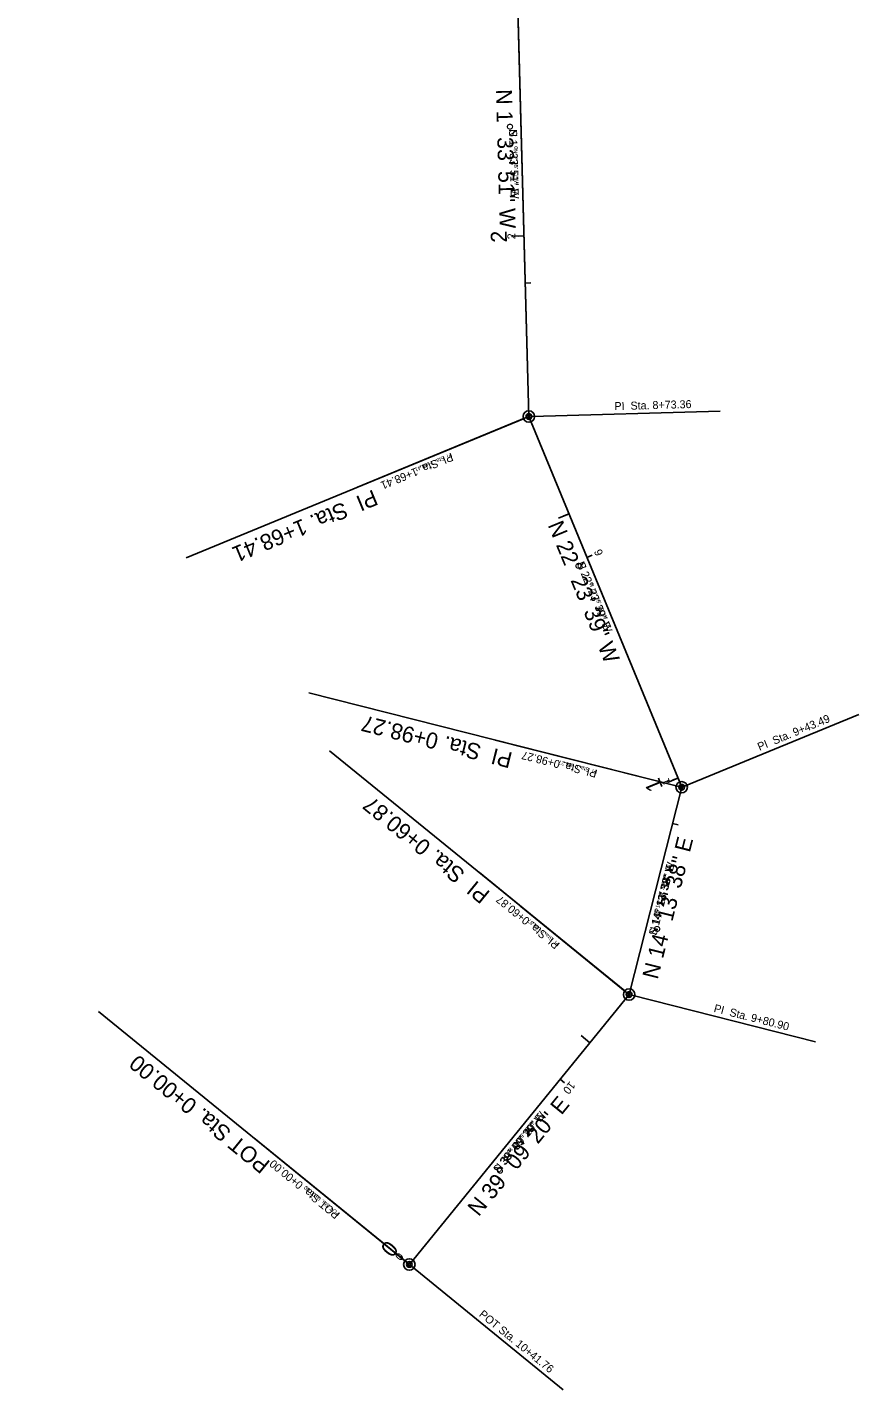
# Model space of a CAD drawing. Extents: x 2261207 to 2264340, y 653057 to 655601.
# Drawn here: x 2261628.8 to 2261774.1, y 654744.8 to 654983.1 of the extents above; entities that cross this region are included whole.
import ezdxf

# ---------------------------------------------------------------- set-up
doc = ezdxf.new("R2010")
doc.units = 0
for name, color, linetype in [('CL_X_Construction', 7, 'Continuous'), ('Default', 7, 'Continuous'), ('GE_X_CL_10', 7, 'Continuous'), ('GE_X_CL_20', 7, 'Continuous'), ('GE_X_CL_5', 7, 'Continuous'), ('SC_Scratch1', 7, 'Continuous'), ('SC_Scratch10', 7, 'Continuous'), ('SC_Scratch2', 7, 'Continuous')]:
    doc.layers.add(name, color=color, linetype=linetype)

msp = doc.modelspace()

# ---------------------------------------------------------------- linework, layer by layer
at = {"layer": 'CL_X_Construction'}
for p, q in [((2261716.47, 654914.99), (2261714.11, 655001.6)), ((2261716.47, 654914.99), (2261714.11, 655001.6)), ((2261743.19, 654850.14), (2261716.47, 654914.99)), ((2261743.19, 654850.14), (2261716.47, 654914.99)), ((2261734, 654813.88), (2261743.19, 654850.14)), ((2261734, 654813.88), (2261743.19, 654850.14)), ((2261695.57, 654766.68), (2261734, 654813.88)), ((2261695.57, 654766.68), (2261734, 654813.88))]:
    msp.add_line(p, q, dxfattribs=at)
at = {"layer": 'Default'}
msp.add_lwpolyline([(2261628.76, 655226.06), (2261663.66, 655187.52), (2261687.58, 655078.76), (2261687.58, 655078.76), (2261714.11, 655001.6), (2261716.47, 654914.99), (2261743.19, 654850.14), (2261734, 654813.88), (2261695.57, 654766.68)], dxfattribs=at)
at = {"layer": 'GE_X_CL_10'}
for p, q in [((2261716.47, 654914.99), (2261714.11, 655001.6)), ((2261715.61, 654946.57), (2261714.61, 654946.54)), ((2261716.01, 654914.8), (2261686.5, 654902.64)), ((2261743.19, 654850.14), (2261716.47, 654914.99)), ((2261723.49, 654897.97), (2261722.56, 654897.59)), ((2261742.71, 654850.26), (2261710.6, 654858.4)), ((2261742.54, 654851.74), (2261741.61, 654851.36)), ((2261734, 654813.88), (2261743.19, 654850.14)), ((2261733.61, 654814.2), (2261707.81, 654835.21)), ((2261695.57, 654766.68), (2261734, 654813.88)), ((2261727.14, 654805.45), (2261726.37, 654806.09)), ((2261695.18, 654767), (2261668.4, 654788.81)), ((2261695.57, 654766.68), (2261694.79, 654767.31))]:
    msp.add_line(p, q, dxfattribs=at)
for centre in [(2261716.47, 654914.99), (2261743.19, 654850.14), (2261734, 654813.88), (2261695.57, 654766.68)]:
    msp.add_circle(centre, 0.5, dxfattribs=at)
at = {"layer": 'GE_X_CL_20'}
for p, q in [((2261716.47, 654914.99), (2261714.11, 655001.6)), ((2261716.47, 654914.99), (2261714.11, 655001.6)), ((2261715.61, 654946.57), (2261713.61, 654946.51)), ((2261715.61, 654946.57), (2261713.61, 654946.51)), ((2261715.61, 654946.57), (2261713.61, 654946.51)), ((2261715.61, 654946.57), (2261713.61, 654946.51)), ((2261743.19, 654850.14), (2261716.47, 654914.99)), ((2261743.19, 654850.14), (2261716.47, 654914.99)), ((2261715.55, 654914.61), (2261656.53, 654890.29)), ((2261715.55, 654914.61), (2261656.53, 654890.29)), ((2261715.55, 654914.61), (2261656.53, 654890.29)), ((2261715.55, 654914.61), (2261656.53, 654890.29)), ((2261723.49, 654897.97), (2261721.64, 654897.2)), ((2261723.49, 654897.97), (2261721.64, 654897.2)), ((2261723.49, 654897.97), (2261721.64, 654897.2)), ((2261723.49, 654897.97), (2261721.64, 654897.2)), ((2261742.23, 654850.38), (2261678.01, 654866.66)), ((2261742.23, 654850.38), (2261678.01, 654866.66)), ((2261742.23, 654850.38), (2261678.01, 654866.66)), ((2261742.23, 654850.38), (2261678.01, 654866.66)), ((2261733.23, 654814.51), (2261681.62, 654856.54)), ((2261733.23, 654814.51), (2261681.62, 654856.54)), ((2261733.23, 654814.51), (2261681.62, 654856.54)), ((2261733.23, 654814.51), (2261681.62, 654856.54)), ((2261742.54, 654851.74), (2261740.69, 654850.97)), ((2261742.54, 654851.74), (2261740.69, 654850.97)), ((2261742.54, 654851.74), (2261740.69, 654850.97)), ((2261742.54, 654851.74), (2261740.69, 654850.97)), ((2261734, 654813.88), (2261743.19, 654850.14)), ((2261734, 654813.88), (2261743.19, 654850.14)), ((2261695.57, 654766.68), (2261734, 654813.88)), ((2261695.57, 654766.68), (2261734, 654813.88)), ((2261694.79, 654767.31), (2261641.22, 654810.94)), ((2261694.79, 654767.31), (2261641.22, 654810.94)), ((2261694.79, 654767.31), (2261641.22, 654810.94)), ((2261694.79, 654767.31), (2261641.22, 654810.94)), ((2261727.14, 654805.45), (2261725.59, 654806.72)), ((2261727.14, 654805.45), (2261725.59, 654806.72)), ((2261727.14, 654805.45), (2261725.59, 654806.72)), ((2261727.14, 654805.45), (2261725.59, 654806.72)), ((2261695.57, 654766.68), (2261694.02, 654767.95)), ((2261695.57, 654766.68), (2261694.02, 654767.95)), ((2261695.57, 654766.68), (2261694.02, 654767.95)), ((2261695.57, 654766.68), (2261694.02, 654767.95))]:
    msp.add_line(p, q, dxfattribs=at)
for centre in [(2261716.47, 654914.99), (2261716.47, 654914.99), (2261716.47, 654914.99), (2261716.47, 654914.99), (2261743.19, 654850.14), (2261743.19, 654850.14), (2261743.19, 654850.14), (2261743.19, 654850.14), (2261734, 654813.88), (2261734, 654813.88), (2261734, 654813.88), (2261734, 654813.88), (2261695.57, 654766.68), (2261695.57, 654766.68), (2261695.57, 654766.68), (2261695.57, 654766.68)]:
    msp.add_circle(centre, 1, dxfattribs=at)
at = {"layer": 'GE_X_CL_5'}
for p, q in [((2261716.47, 654914.99), (2261714.11, 655001.6)), ((2261715.61, 654946.57), (2261714.61, 654946.54)), ((2261716.01, 654914.8), (2261694.85, 654906.08)), ((2261743.19, 654850.14), (2261716.47, 654914.99)), ((2261723.49, 654897.97), (2261722.56, 654897.59)), ((2261742.71, 654850.26), (2261719.67, 654856.1)), ((2261742.54, 654851.74), (2261741.61, 654851.36)), ((2261734, 654813.88), (2261743.19, 654850.14)), ((2261733.61, 654814.2), (2261715.08, 654829.29)), ((2261695.57, 654766.68), (2261734, 654813.88)), ((2261727.14, 654805.45), (2261726.37, 654806.09)), ((2261695.18, 654767), (2261676.3, 654782.37)), ((2261695.57, 654766.68), (2261694.79, 654767.31))]:
    msp.add_line(p, q, dxfattribs=at)
for centre in [(2261716.47, 654914.99), (2261743.19, 654850.14), (2261734, 654813.88), (2261695.57, 654766.68)]:
    msp.add_circle(centre, 0.25, dxfattribs=at)
at = {"layer": 'SC_Scratch1'}
for p, q in [((2261714.11, 655001.6), (2261716.47, 654914.99)), ((2261716.47, 654914.99), (2261743.19, 654850.14)), ((2261743.19, 654850.14), (2261734, 654813.88)), ((2261734, 654813.88), (2261695.57, 654766.68))]:
    msp.add_line(p, q, dxfattribs=at)
at = {"layer": 'SC_Scratch10'}
for p, q in [((2261714.11, 655001.6), (2261716.47, 654914.99)), ((2261716.47, 654914.99), (2261743.19, 654850.14)), ((2261743.19, 654850.14), (2261734, 654813.88)), ((2261734, 654813.88), (2261695.57, 654766.68))]:
    msp.add_line(p, q, dxfattribs=at)
at = {"layer": 'SC_Scratch2'}
for p, q in [((2261714.11, 655001.6), (2261716.47, 654914.99)), ((2261715.84, 654938.33), (2261716.84, 654938.36)), ((2261715.84, 654938.33), (2261716.84, 654938.36)), ((2261716.47, 654914.99), (2261743.19, 654850.14)), ((2261716.97, 654915), (2261749.92, 654915.9)), ((2261716.97, 654915), (2261749.92, 654915.9)), ((2261726.62, 654890.35), (2261727.55, 654890.73)), ((2261726.62, 654890.35), (2261727.55, 654890.73)), ((2261743.66, 654850.33), (2261774.15, 654862.89)), ((2261743.66, 654850.33), (2261774.15, 654862.89)), ((2261743.19, 654850.14), (2261734, 654813.88)), ((2261741.6, 654843.83), (2261742.57, 654843.59)), ((2261741.6, 654843.83), (2261742.57, 654843.59)), ((2261734, 654813.88), (2261695.57, 654766.68)), ((2261734.49, 654813.76), (2261766.61, 654805.61)), ((2261734.49, 654813.76), (2261766.61, 654805.61)), ((2261721.94, 654799.07), (2261722.72, 654798.44)), ((2261721.94, 654799.07), (2261722.72, 654798.44)), ((2261695.96, 654766.37), (2261722.49, 654744.77)), ((2261695.96, 654766.37), (2261722.49, 654744.77))]:
    msp.add_line(p, q, dxfattribs=at)
for centre in [(2261716.47, 654914.99), (2261716.47, 654914.99), (2261743.19, 654850.14), (2261743.19, 654850.14), (2261734, 654813.88), (2261734, 654813.88), (2261695.57, 654766.68), (2261695.57, 654766.68)]:
    msp.add_circle(centre, 0.5, dxfattribs=at)

# ---------------------------------------------------------------- texts
at = {"layer": 'GE_X_CL_10'}
for s, rotation, p in [('N 1%%d 33\' 51" W', 271.5641, (2261713, 654965.24)), ('2', 91.5641, (2261714.13, 654946)), ('PI  Sta. 1+68.41', 202.3942, (2261702.87, 654908.62)), ('N 22%%d 23\' 39" W', 292.3942, (2261724.79, 654889.29)), ('PI  Sta. 0+98.27', 165.7727, (2261728.48, 654853.15)), ('1', 112.3942, (2261741.26, 654850.9)), ('N 14%%d 13\' 38" E', 75.7727, (2261738.79, 654824.21)), ('PI  Sta. 0+60.87', 140.8444, (2261721.93, 654822.81)), ('N 39%%d 09\' 20" E', 50.8444, (2261711.24, 654782.61)), ('POT Sta. 0+00.00', 140.8444, (2261683.5, 654775.61)), ('0', 50.8444, (2261694.05, 654767.2))]:
    msp.add_text(s, height=1.4, rotation=rotation, dxfattribs=at).set_placement(p)
at = {"layer": 'GE_X_CL_20'}
for s, rotation, p in [('N 1%%d 33\' 51" W', 271.5641, (2261710.71, 654972.19)), ('N 1%%d 33\' 51" W', 271.5641, (2261710.71, 654972.19)), ('2', 91.5641, (2261712.64, 654945.44)), ('2', 91.5641, (2261712.64, 654945.44)), ('2', 91.5641, (2261712.64, 654945.44)), ('2', 91.5641, (2261712.64, 654945.44)), ('PI  Sta. 1+68.41', 202.3942, (2261689.27, 654902.26)), ('PI  Sta. 1+68.41', 202.3942, (2261689.27, 654902.26)), ('PI  Sta. 1+68.41', 202.3942, (2261689.27, 654902.26)), ('PI  Sta. 1+68.41', 202.3942, (2261689.27, 654902.26)), ('N 22%%d 23\' 39" W', 292.3942, (2261719.74, 654896.02)), ('N 22%%d 23\' 39" W', 292.3942, (2261719.74, 654896.02)), ('PI  Sta. 0+98.27', 165.7727, (2261713.77, 654856.15)), ('PI  Sta. 0+98.27', 165.7727, (2261713.77, 654856.15)), ('PI  Sta. 0+98.27', 165.7727, (2261713.77, 654856.15)), ('PI  Sta. 0+98.27', 165.7727, (2261713.77, 654856.15)), ('1', 112.3942, (2261739.98, 654850.06)), ('1', 112.3942, (2261739.98, 654850.06)), ('1', 112.3942, (2261739.98, 654850.06)), ('1', 112.3942, (2261739.98, 654850.06)), ('PI  Sta. 0+60.87', 140.8444, (2261709.86, 654831.74)), ('PI  Sta. 0+60.87', 140.8444, (2261709.86, 654831.74)), ('PI  Sta. 0+60.87', 140.8444, (2261709.86, 654831.74)), ('PI  Sta. 0+60.87', 140.8444, (2261709.86, 654831.74)), ('N 14%%d 13\' 38" E', 75.7727, (2261738.98, 654816.42)), ('N 14%%d 13\' 38" E', 75.7727, (2261738.98, 654816.42)), ('POT Sta. 0+00.00', 140.8444, (2261671.42, 654784.54)), ('POT Sta. 0+00.00', 140.8444, (2261671.42, 654784.54)), ('POT Sta. 0+00.00', 140.8444, (2261671.42, 654784.54)), ('POT Sta. 0+00.00', 140.8444, (2261671.42, 654784.54)), ('N 39%%d 09\' 20" E', 50.8444, (2261707.7, 654774.93)), ('N 39%%d 09\' 20" E', 50.8444, (2261707.7, 654774.93)), ('0', 50.8444, (2261692.54, 654767.71)), ('0', 50.8444, (2261692.54, 654767.71)), ('0', 50.8444, (2261692.54, 654767.71)), ('0', 50.8444, (2261692.54, 654767.71))]:
    msp.add_text(s, height=2.8, rotation=rotation, dxfattribs=at).set_placement(p)
at = {"layer": 'GE_X_CL_5'}
for s, rotation, p in [('N 1%%d 33\' 51" W', 271.5641, (2261713.8, 654961.71)), ('2', 91.5641, (2261714.12, 654946.26)), ('PI  Sta. 1+68.41', 202.3942, (2261702.87, 654908.62)), ('N 22%%d 23\' 39" W', 292.3942, (2261727.01, 654885.75)), ('PI  Sta. 0+98.27', 165.7727, (2261728.48, 654853.15)), ('1', 112.3942, (2261741.18, 654851.08)), ('N 14%%d 13\' 38" E', 75.7727, (2261739.03, 654828.02)), ('PI  Sta. 0+60.87', 140.8444, (2261721.93, 654822.81)), ('N 39%%d 09\' 20" E', 50.8444, (2261713.29, 654786.22)), ('POT Sta. 0+00.00', 140.8444, (2261683.5, 654775.61)), ('0', 50.8444, (2261694.25, 654767.44))]:
    msp.add_text(s, height=0.7, rotation=rotation, dxfattribs=at).set_placement(p)
at = {"layer": 'SC_Scratch2'}
for s, rotation, p in [('S 1%%d 33\' 51" E', 271.5641, (2261713, 654965.12)), ('PI  Sta. 8+73.36', 1.5641, (2261731.45, 654916.1)), ('PI  Sta. 8+73.36', 1.5641, (2261731.45, 654916.1)), ('9', 292.3942, (2261727.81, 654891.41)), ('9', 292.3942, (2261727.81, 654891.41)), ('S 22%%d 23\' 39" E', 292.3942, (2261724.84, 654889.18)), ('PI  Sta. 9+43.49', 22.3942, (2261756.8, 654856.5)), ('PI  Sta. 9+43.49', 22.3942, (2261756.8, 654856.5)), ('S 14%%d 13\' 38" W', 75.7727, (2261738.77, 654824.12)), ('PI  Sta. 9+80.90', 345.7727, (2261748.71, 654810.87)), ('PI  Sta. 9+80.90', 345.7727, (2261748.71, 654810.87)), ('10', 230.8444, (2261723.66, 654798.81)), ('10', 230.8444, (2261723.66, 654798.81)), ('S 39%%d 09\' 20" W', 50.8444, (2261711.18, 654782.53)), ('POT Sta. 10+41.76', 320.8444, (2261707.64, 654757.75)), ('POT Sta. 10+41.76', 320.8444, (2261707.64, 654757.75))]:
    msp.add_text(s, height=1.4, rotation=rotation, dxfattribs=at).set_placement(p)

doc.saveas('drawing.dxf')
